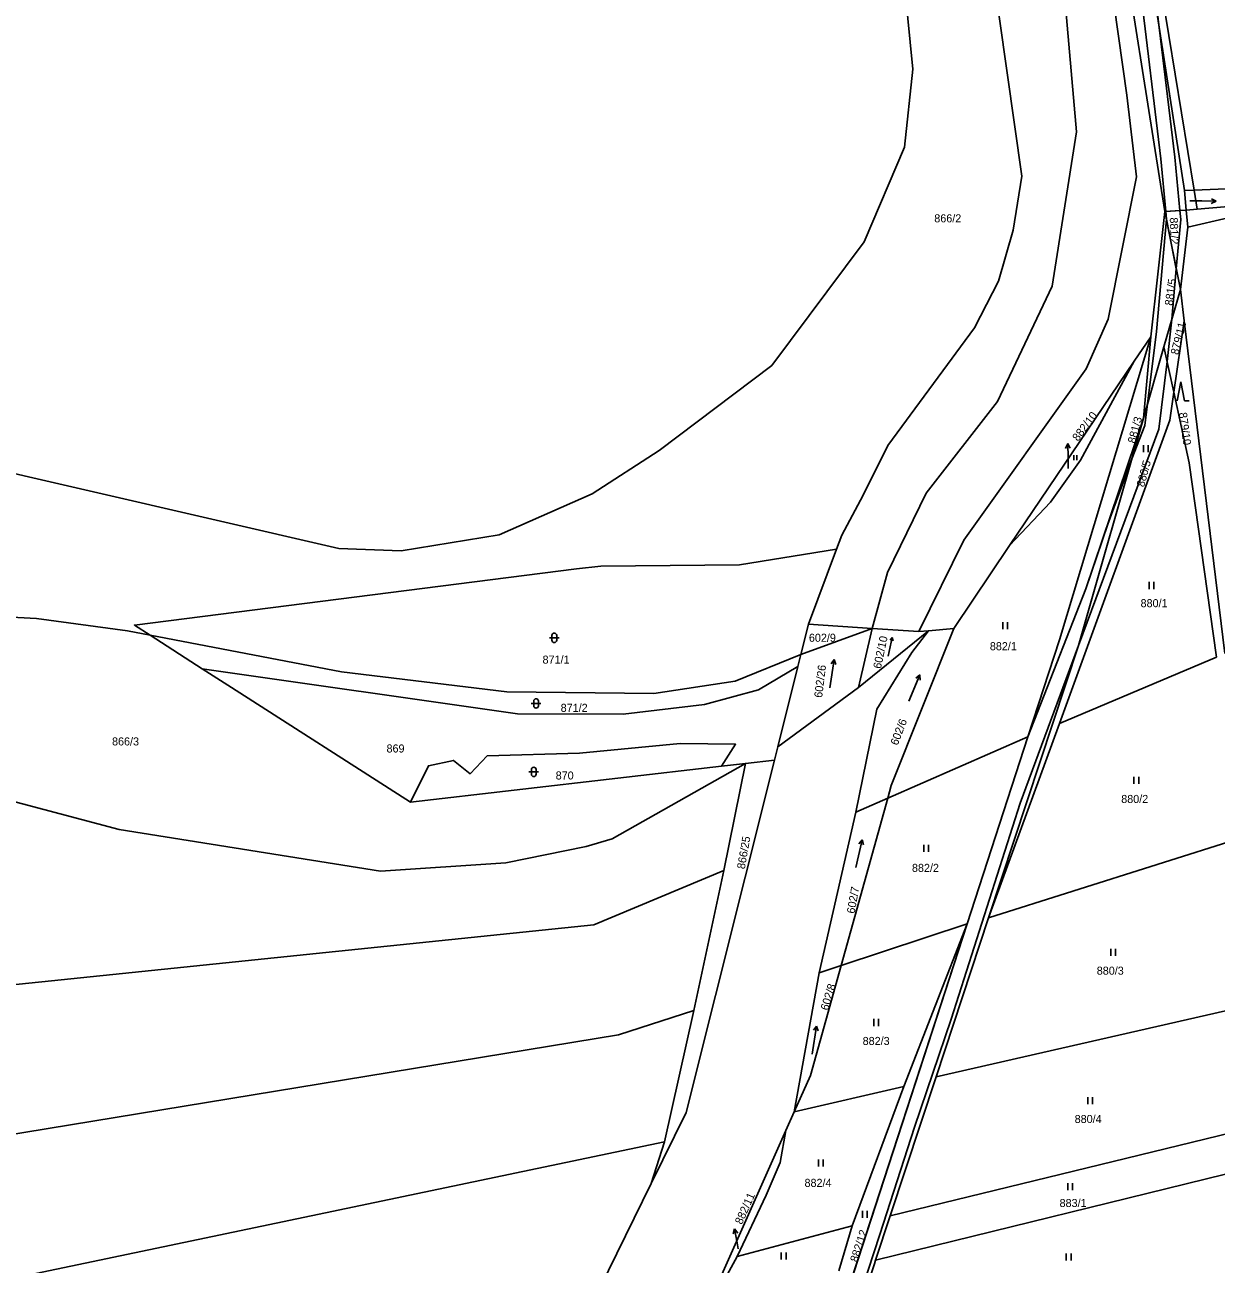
# Model space of a CAD drawing. Extents: x -757266 to -753360, y -1162585 to -1157740.
# Drawn here: x -756892.7 to -756641.4, y -1159095.7 to -1158834.4 of the extents above; entities that cross this region are included whole.
import ezdxf

# ---------------------------------------------------------------- set-up
doc = ezdxf.new("R2010")
doc.units = 0
for name, color, linetype in [('Hranice parcel', 7, 'Continuous'), ('Parcelní čísla', 7, 'Continuous'), ('Pop  PČ popisy', 7, 'Continuous'), ('Věcná břemena k části', 7, 'Continuous'), ('Značky kultur', 7, 'Continuous')]:
    doc.layers.add(name, color=color, linetype=linetype)

msp = doc.modelspace()

# ---------------------------------------------------------------- linework, layer by layer
at = {"layer": 'Hranice parcel'}
for p, q in [((-756652.23, -1158873.75), (-756670.96, -1158755.67)), ((-756646.09, -1158869.26), (-756655.33, -1158812.59)), ((-756646.09, -1158869.26), (-756648.09, -1158869.34)), ((-756648.09, -1158869.34), (-756647.71, -1158873.46)), ((-756646.09, -1158869.26), (-756645.44, -1158873.27)), ((-756655.23, -1158900.19), (-756652.23, -1158873.75)), ((-756647.71, -1158873.46), (-756652.23, -1158873.75)), ((-756652.23, -1158873.75), (-756648.97, -1158890.2)), ((-756647.71, -1158873.46), (-756645.44, -1158873.27)), ((-756647.37, -1158877.07), (-756647.71, -1158873.46)), ((-756647.37, -1158877.07), (-756638.9, -1158875.09)), ((-756648.97, -1158890.2), (-756647.37, -1158877.07)), ((-756652.43, -1158902.28), (-756648.97, -1158890.2)), ((-756648.97, -1158890.2), (-756648.16, -1158896.81)), ((-756648.16, -1158896.81), (-756650.33, -1158911.89)), ((-756648.16, -1158896.81), (-756639.58, -1158966.96)), ((-756658.69, -1158905.31), (-756655.23, -1158900.19)), ((-756655.23, -1158900.19), (-756656.75, -1158917.37)), ((-756656.75, -1158917.37), (-756652.43, -1158902.28)), ((-756652.43, -1158902.28), (-756650.33, -1158911.89)), ((-756684.98, -1158944.22), (-756658.69, -1158905.31)), ((-756721.53, -1158944.96), (-756727.41, -1158960.79)), ((-756696.78, -1158961.69), (-756684.98, -1158944.22)), ((-756727.41, -1158960.79), (-756729.02, -1158967.21)), ((-756729.02, -1158967.21), (-756714.01, -1158961.69)), ((-756714.01, -1158961.69), (-756727.41, -1158960.79)), ((-756714.01, -1158961.69), (-756716.85, -1158974.11)), ((-756714.01, -1158961.69), (-756704.1, -1158962.35)), ((-756702.06, -1158962.17), (-756696.78, -1158961.69)), ((-756855.31, -1158970.19), (-756866.26, -1158963.14)), ((-756702.06, -1158962.17), (-756716.85, -1158974.11)), ((-756704.1, -1158962.35), (-756702.06, -1158962.17)), ((-756729.02, -1158967.21), (-756729.65, -1158969.7)), ((-756674.43, -1158981.73), (-756641.37, -1158967.72)), ((-756733.89, -1158986.62), (-756729.65, -1158969.7)), ((-756716.85, -1158974.11), (-756733.89, -1158986.62)), ((-756674.43, -1158981.73), (-756689.42, -1159022.71)), ((-756681.12, -1158984.56), (-756710.68, -1158997.47)), ((-756693.94, -1159023.94), (-756681.12, -1158984.56)), ((-756734.59, -1158989.43), (-756733.89, -1158986.62)), ((-756745.79, -1158990.73), (-756740.71, -1158990.14)), ((-756745.26, -1159012.75), (-756740.71, -1158990.14)), ((-756740.71, -1158990.14), (-756734.59, -1158989.43)), ((-756811.36, -1158998.34), (-756745.79, -1158990.73)), ((-756710.68, -1158997.47), (-756720.53, -1159032.78)), ((-756717.42, -1159000.41), (-756710.68, -1158997.47)), ((-756725.18, -1159034.33), (-756717.42, -1159000.41)), ((-756636.06, -1159005.83), (-756689.42, -1159022.71)), ((-756751.59, -1159042.28), (-756745.26, -1159012.75)), ((-756720.53, -1159032.78), (-756693.94, -1159023.94)), ((-756707.27, -1159058.26), (-756693.94, -1159023.94)), ((-756689.42, -1159022.71), (-756700.49, -1159056.25)), ((-756730.4, -1159063.58), (-756725.18, -1159034.33)), ((-756725.18, -1159034.33), (-756720.53, -1159032.78)), ((-756757.78, -1159069.91), (-756751.59, -1159042.28)), ((-756700.49, -1159056.25), (-756631.23, -1159040.46)), ((-756730.4, -1159063.58), (-756707.27, -1159058.26)), ((-756718.19, -1159087.63), (-756707.27, -1159058.26)), ((-756700.49, -1159056.25), (-756710.16, -1159085.54)), ((-756732.16, -1159067.53), (-756730.4, -1159063.58)), ((-756710.16, -1159085.54), (-756627.75, -1159065.45)), ((-756750.64, -1159108.95), (-756732.16, -1159067.53)), ((-756760.56, -1159078.72), (-756757.78, -1159069.91)), ((-756713.24, -1159094.88), (-756626.62, -1159073.56)), ((-756760.56, -1159078.72), (-756771.42, -1159100.8)), ((-756710.16, -1159085.54), (-756713.24, -1159094.88)), ((-756742.44, -1159094.15), (-756718.19, -1159087.63)), ((-756721.04, -1159097.16), (-756718.19, -1159087.63)), ((-756742.44, -1159094.15), (-756747.61, -1159103.48))]:
    msp.add_line(p, q, dxfattribs=at)
for points in [[(-756704.1, -1158962.35), (-756694.65, -1158943.1), (-756668.85, -1158906.92), (-756664.23, -1158896.45), (-756658.19, -1158866.49), (-756660.27, -1158849.21), (-756665.64, -1158810.88), (-756675.54, -1158767.56), (-756690.59, -1158747.65), (-756703.99, -1158734.09), (-756739.28, -1158704.77), (-756778.11, -1158672.96), (-756800.91, -1158652.49), (-756808.06, -1158644.98), (-756837.14, -1158613.12), (-756852.08, -1158598.85), (-756854.12, -1158598.67)], [(-756855.85, -1158604.43), (-756855.66, -1158605.6), (-756849.02, -1158617.31), (-756822.52, -1158645.02), (-756802.38, -1158664.92), (-756770.02, -1158692.69), (-756737.67, -1158719.39), (-756714.1, -1158739.48), (-756691.47, -1158762.44), (-756680.95, -1158786.54), (-756673.45, -1158827.18), (-756670.9, -1158856.95), (-756675.99, -1158889.53), (-756687.57, -1158913.81), (-756702.57, -1158933.17), (-756710.72, -1158949.9), (-756714.01, -1158961.69)], [(-756837.25, -1158648.02), (-756818.28, -1158669.16), (-756794.81, -1158689.33), (-756766.53, -1158712.65), (-756737.54, -1158736.42), (-756723.38, -1158748.43), (-756711, -1158760.37), (-756702.94, -1158769.11), (-756696.88, -1158778.68), (-756693.44, -1158789.52), (-756688.63, -1158822.2), (-756682.44, -1158866.3), (-756684.21, -1158877.7), (-756687.33, -1158888.47), (-756692.42, -1158898.28), (-756710.7, -1158923.09), (-756715.87, -1158933.58), (-756720.37, -1158942.01), (-756721.53, -1158944.96)], [(-756727.91, -1158654.4), (-756709.44, -1158665.92), (-756666.01, -1158753.76), (-756648.09, -1158869.34)], [(-756983.62, -1158931.02), (-756954.43, -1158925.85), (-756930.22, -1158924.74), (-756906.02, -1158926.48), (-756826.44, -1158944.84), (-756813.31, -1158945.31), (-756792.67, -1158941.97), (-756773.06, -1158933.3), (-756758.92, -1158924.18), (-756735.15, -1158906.25), (-756715.69, -1158880.17), (-756707.15, -1158860.22), (-756705.41, -1158843.76), (-756708.08, -1158816.65), (-756718.38, -1158798.31), (-756761.04, -1158758.83), (-756811.19, -1158729.08), (-756866.34, -1158689.98), (-756876.64, -1158666.26)], [(-756512.34, -1158859.34), (-756514.13, -1158859.65), (-756573.98, -1158866.27), (-756646.09, -1158869.26)], [(-756645.44, -1158873.27), (-756610.86, -1158870.36), (-756511.01, -1158864.42)], [(-756655.23, -1158900.19), (-756674.47, -1158964.12), (-756681.12, -1158984.56)], [(-756658.69, -1158905.31), (-756670.03, -1158926.21), (-756676.37, -1158935.03), (-756684.98, -1158944.22)], [(-756650.33, -1158911.89), (-756651.17, -1158917.74), (-756674.43, -1158981.73)], [(-756650.33, -1158911.89), (-756647.08, -1158926.76), (-756641.37, -1158967.72)], [(-756656.75, -1158917.37), (-756670.46, -1158965.27), (-756689.42, -1159022.71)], [(-756656.75, -1158917.37), (-756668.88, -1158953.33), (-756681.12, -1158984.56)], [(-756866.26, -1158963.14), (-756869.59, -1158960.99), (-756776.34, -1158949.13), (-756771.21, -1158948.55), (-756741.99, -1158948.27), (-756721.53, -1158944.96)], [(-757010.57, -1158989.58), (-756976.17, -1158970.73), (-756946.1, -1158962.81), (-756929.75, -1158959.65), (-756913.93, -1158958.33), (-756890.23, -1158959.62), (-756871.05, -1158962.22), (-756866.26, -1158963.14)], [(-756710.68, -1158997.47), (-756709.94, -1158994.81), (-756696.78, -1158961.69)], [(-756866.26, -1158963.14), (-756825.9, -1158970.85), (-756791.02, -1158975.08), (-756760.05, -1158975.38), (-756742.86, -1158972.81), (-756729.02, -1158967.21)], [(-756717.42, -1159000.41), (-756713.02, -1158978.73), (-756705.62, -1158966.74), (-756702.06, -1158962.17)], [(-756729.65, -1158969.7), (-756737.93, -1158974.6), (-756749.35, -1158977.73), (-756766.53, -1158979.78), (-756788.77, -1158979.71), (-756855.31, -1158970.19)], [(-756855.31, -1158970.19), (-756849.11, -1158974.11), (-756811.36, -1158998.34)], [(-757015.52, -1158999.82), (-756999.4, -1158992.84), (-756976.02, -1158986.33), (-756955.93, -1158985.48), (-756917.1, -1158992.37), (-756872.78, -1159004.07), (-756817.66, -1159012.84), (-756791.26, -1159011.14), (-756774.29, -1159007.65), (-756768.82, -1159006.05), (-756740.71, -1158990.14)], [(-756811.36, -1158998.34), (-756807.58, -1158990.64), (-756802.29, -1158989.51), (-756798.79, -1158992.31), (-756795.2, -1158988.55), (-756775.74, -1158988.02), (-756754.48, -1158985.92), (-756742.77, -1158986.1), (-756745.79, -1158990.73)], [(-756734.59, -1158989.43), (-756753.21, -1159063.76), (-756760.56, -1159078.72)], [(-757041.03, -1159053.22), (-756943.68, -1159041.8), (-756772.7, -1159024.16), (-756745.26, -1159012.75)], [(-756693.94, -1159023.94), (-756730.98, -1159137.79), (-756735.86, -1159145.36)], [(-756730.4, -1159063.58), (-756726.99, -1159055.94), (-756720.53, -1159032.78)], [(-757061.64, -1159095.67), (-756767.49, -1159047.37), (-756751.59, -1159042.28)], [(-756732.16, -1159067.53), (-756733.38, -1159074.33), (-756736.3, -1159081.22), (-756742.44, -1159094.15)], [(-757082.79, -1159139.21), (-756930.71, -1159106.11), (-756757.78, -1159069.91)], [(-756713.24, -1159094.88), (-756713.51, -1159095.69), (-756721.27, -1159119.03)]]:
    msp.add_lwpolyline(points, dxfattribs=at)
at = {"layer": 'Pop  PČ popisy'}
for p, q in [((-756646.94, -1158871.51), (-756644.44, -1158871.55)), ((-756644.44, -1158871.55), (-756641.439, -1158871.602)), ((-756641.439, -1158871.602), (-756642.45, -1158872.086)), ((-756641.439, -1158871.602), (-756642.432, -1158871.084)), ((-756672.712, -1158922.709), (-756673.196, -1158923.72)), ((-756672.66, -1158925.71), (-756672.712, -1158922.709)), ((-756672.712, -1158922.709), (-756672.194, -1158923.702)), ((-756672.61, -1158927.93), (-756672.66, -1158925.71)), ((-756742.991, -1159088.265), (-756743.31, -1159089.338)), ((-756742.47, -1159091.22), (-756742.991, -1159088.265)), ((-756742.991, -1159088.265), (-756742.324, -1159089.164)), ((-756742.24, -1159092.53), (-756742.47, -1159091.22))]:
    msp.add_line(p, q, dxfattribs=at)
at = {"layer": 'Věcná břemena k části'}
for points in [[(-756667.62, -1158750.51), (-756670.2, -1158743.36), (-756675.23, -1158732.28), (-756680.53, -1158721.17), (-756702.61, -1158677.27), (-756704.02, -1158676.88), (-756710.63, -1158675.04), (-756708.76, -1158678.69), (-756704.69, -1158679.81), (-756683.23, -1158722.47), (-756677.93, -1158733.58), (-756672.98, -1158744.49), (-756668.78, -1158756.12), (-756659.04, -1158815.21), (-756657.41, -1158827.02), (-756653.08, -1158862.64), (-756652.06, -1158873.74), (-756649.07, -1158873.55), (-756650.1, -1158862.28), (-756653.42, -1158834.94), (-756654.43, -1158826.66), (-756656.07, -1158814.76), (-756665.77, -1158755.32)], [(-756693.94, -1159023.94), (-756726.09, -1159122.77), (-756723.71, -1159123.57), (-756716.11, -1159100.85), (-756712.39, -1159089.47), (-756705.05, -1159066.86), (-756697.28, -1159044.1), (-756682.79, -1158998.51), (-756670.46, -1158965.27), (-756653.5, -1158919.64), (-756651.75, -1158905.38), (-756650.76, -1158896.46), (-756649.82, -1158885.89), (-756651.9, -1158875.42), (-756654, -1158899.09), (-756655.87, -1158914.31), (-756656.44, -1158918.88), (-756659.19, -1158925.91), (-756664.27, -1158939.67), (-756668.88, -1158953.33), (-756681.12, -1158984.56)], [(-756652.06, -1158873.74), (-756651.9, -1158875.42), (-756649.82, -1158885.89), (-756648.9, -1158875.46), (-756649.07, -1158873.55)]]:
    msp.add_lwpolyline(points, close=True, dxfattribs=at)
at = {"layer": 'Značky kultur'}
for p, q in [((-756648.88, -1158909.68), (-756649.63, -1158913.68)), ((-756648.13, -1158913.68), (-756648.88, -1158909.68)), ((-756648.13, -1158913.68), (-756647.134, -1158913.68)), ((-756671.462, -1158926.19), (-756671.462, -1158925.185)), ((-756670.792, -1158926.19), (-756670.792, -1158925.185)), ((-756656.771, -1158924.51), (-756656.771, -1158923.01)), ((-756655.77, -1158924.51), (-756655.77, -1158923.01)), ((-756655.561, -1158953.38), (-756655.561, -1158951.88)), ((-756654.56, -1158953.38), (-756654.56, -1158951.88)), ((-756686.431, -1158961.84), (-756686.431, -1158960.34)), ((-756685.43, -1158961.84), (-756685.43, -1158960.34)), ((-756782.021, -1158963.661), (-756780.019, -1158963.661)), ((-756781.521, -1158963.161), (-756781.521, -1158964.162)), ((-756780.519, -1158964.162), (-756780.519, -1158963.161)), ((-756710.58, -1158967.526), (-756709.744, -1158963.594)), ((-756709.744, -1158963.594), (-756710.209, -1158964.164)), ((-756709.744, -1158963.594), (-756709.552, -1158964.304)), ((-756722.898, -1158974.177), (-756721.96, -1158968.251)), ((-756721.96, -1158968.251), (-756722.608, -1158969.138)), ((-756721.96, -1158968.251), (-756721.617, -1158969.295)), ((-756706.268, -1158976.999), (-756703.923, -1158971.476)), ((-756703.923, -1158971.476), (-756704.767, -1158972.18)), ((-756703.923, -1158971.476), (-756703.843, -1158972.571)), ((-756785.871, -1158977.501), (-756783.869, -1158977.501)), ((-756785.371, -1158977.001), (-756785.371, -1158978.002)), ((-756784.369, -1158978.002), (-756784.369, -1158977.001)), ((-756786.361, -1158991.941), (-756784.359, -1158991.941)), ((-756785.861, -1158991.441), (-756785.861, -1158992.442)), ((-756784.859, -1158992.442), (-756784.859, -1158991.441)), ((-756658.761, -1158994.45), (-756658.761, -1158992.95)), ((-756657.76, -1158994.45), (-756657.76, -1158992.95)), ((-756717.413, -1159012.078), (-756716.063, -1159006.232)), ((-756716.063, -1159006.232), (-756716.771, -1159007.071)), ((-756716.063, -1159006.232), (-756715.794, -1159007.297)), ((-756703.071, -1159008.82), (-756703.071, -1159007.32)), ((-756702.07, -1159008.82), (-756702.07, -1159007.32)), ((-756663.661, -1159030.74), (-756663.661, -1159029.24)), ((-756662.66, -1159030.74), (-756662.66, -1159029.24)), ((-756713.631, -1159045.52), (-756713.631, -1159044.02)), ((-756712.63, -1159045.52), (-756712.63, -1159044.02)), ((-756726.628, -1159051.447), (-756725.69, -1159045.521)), ((-756725.69, -1159045.521), (-756726.338, -1159046.408)), ((-756725.69, -1159045.521), (-756725.347, -1159046.565)), ((-756668.491, -1159062.01), (-756668.491, -1159060.51)), ((-756667.49, -1159062.01), (-756667.49, -1159060.51)), ((-756725.301, -1159075.14), (-756725.301, -1159073.64)), ((-756724.3, -1159075.14), (-756724.3, -1159073.64)), ((-756672.691, -1159080.15), (-756672.691, -1159078.65)), ((-756671.69, -1159080.15), (-756671.69, -1159078.65)), ((-756716.011, -1159086), (-756716.011, -1159084.5)), ((-756715.01, -1159086), (-756715.01, -1159084.5)), ((-756733.151, -1159094.76), (-756733.151, -1159093.26)), ((-756732.15, -1159094.76), (-756732.15, -1159093.26)), ((-756673.021, -1159094.97), (-756673.021, -1159093.47)), ((-756672.02, -1159094.97), (-756672.02, -1159093.47))]:
    msp.add_line(p, q, dxfattribs=at)
for centre, start, end in [((-756781.02, -1158963.1609), 0, 180), ((-756781.02, -1158964.1609), 180, 359.987886), ((-756784.87, -1158977.0009), 0, 180), ((-756784.87, -1158978.0009), 180, 359.987886), ((-756785.36, -1158991.4409), 0, 180), ((-756785.36, -1158992.4409), 180, 359.987886)]:
    msp.add_arc(centre, 0.5, start, end, dxfattribs=at)

# ---------------------------------------------------------------- texts
at = {"layer": 'Parcelní čísla'}
for s, p in [('866/2', (-756700.87, -1158876.06)), ('880/1', (-756657.36, -1158957.21)), ('602/9', (-756727.32, -1158964.5)), ('882/1', (-756689.15, -1158966.28)), ('871/1', (-756783.5, -1158969.11)), ('871/2', (-756779.68, -1158979.28)), ('866/3', (-756874.31, -1158986.36)), ('869', (-756816.41, -1158987.85)), ('870', (-756780.73, -1158993.54)), ('880/2', (-756661.44, -1158998.49)), ('882/2', (-756705.58, -1159013.03)), ('880/3', (-756666.6, -1159034.7)), ('882/3', (-756715.98, -1159049.52)), ('880/4', (-756671.26, -1159065.97)), ('882/4', (-756728.24, -1159079.44)), ('883/1', (-756674.44, -1159083.69))]:
    msp.add_text(s, height=1.7, dxfattribs=at).set_placement(p)
for s, rotation, p in [('881/2', 272, (-756651.209, -1158875.049)), ('881/5', 82, (-756650.608, -1158893.698)), ('879/11', 76, (-756649.415, -1158904.105)), ('882/10', 53, (-756670.561, -1158922.351)), ('881/3', 75, (-756658.478, -1158922.789)), ('879/10', 278, (-756649.291, -1158916.248)), ('880/5', 75, (-756656.618, -1158931.979)), ('602/10', 78, (-756712.138, -1158970.286)), ('602/26', 83, (-756724.536, -1158976.373)), ('602/6', 68.999997, (-756708.616, -1158986.464)), ('866/25', 80, (-756740.852, -1159012.517)), ('602/7', 80, (-756717.682, -1159021.907)), ('602/8', 73, (-756723.287, -1159042.358)), ('882/11', 66, (-756741.463, -1159087.495)), ('882/12', 72, (-756717.081, -1159095.432))]:
    msp.add_text(s, height=1.7, rotation=rotation, dxfattribs=at).set_placement(p)

doc.saveas('drawing.dxf')
